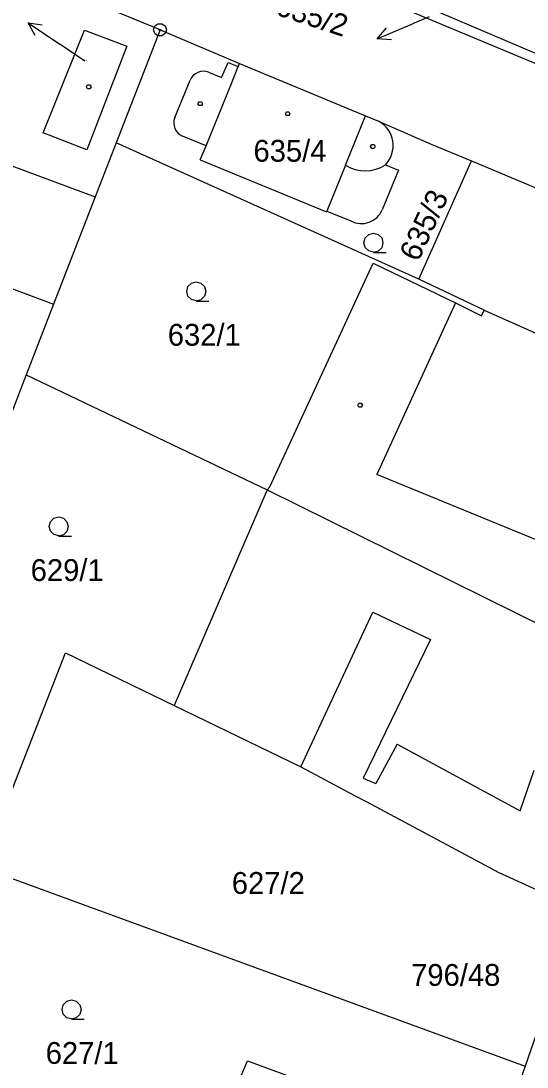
# Model space of a CAD drawing. Extents: x -759060 to -757386, y -1172273 to -1170948.
# Drawn here: x -758101.6 to -758062.1, y -1171430.9 to -1171349.3 of the extents above; entities that cross this region are included whole.
import ezdxf

# ---------------------------------------------------------------- set-up
doc = ezdxf.new("R2010")
doc.units = 0
for name, color, linetype in [('Vrstva 1', 7, 'Continuous'), ('Vrstva 12', 7, 'Continuous'), ('Vrstva 2', 7, 'Continuous'), ('Vrstva 3', 7, 'Continuous'), ('Vrstva 4', 7, 'Continuous'), ('Vrstva 5', 7, 'Continuous'), ('Vrstva 7', 7, 'Continuous'), ('Vrstva 8', 7, 'Continuous')]:
    doc.layers.add(name, color=color, linetype=linetype)

msp = doc.modelspace()

# ---------------------------------------------------------------- linework, layer by layer
at = {"layer": 'Vrstva 1'}
for p, q in [((-758090.74, -1171350.03), (-758125.45, -1171335.56)), ((-758062.42, -1171351.45), (-758087.08, -1171340.96)), ((-758087.4, -1171341.8), (-758056.26, -1171354.83)), ((-758090.74, -1171350.03), (-758094.16, -1171358.84)), ((-758090.74, -1171350.03), (-758084.54, -1171352.65)), ((-758099.84, -1171358.07), (-758096.62, -1171350.05)), ((-758096.62, -1171350.05), (-758093.33, -1171351.31)), ((-758093.33, -1171351.31), (-758096.44, -1171359.39)), ((-758060.58, -1171352.23), (-758062.42, -1171351.45)), ((-758085.96, -1171353.75), (-758085.43, -1171352.58)), ((-758085.43, -1171352.58), (-758084.64, -1171352.9)), ((-758084.64, -1171352.9), (-758084.54, -1171352.65)), ((-758084.54, -1171352.65), (-758074.71, -1171356.73)), ((-758120.75, -1171353.76), (-758095.79, -1171363.05)), ((-758089.59, -1171356.87), (-758088.39, -1171353.95)), ((-758086.95, -1171353.34), (-758085.96, -1171353.75)), ((-758074.71, -1171356.73), (-758073.7, -1171357.15)), ((-758073.7, -1171357.15), (-758069.6, -1171358.93)), ((-758096.44, -1171359.39), (-758099.84, -1171358.07)), ((-758094.16, -1171358.84), (-758095.79, -1171363.05)), ((-758070.57, -1171369.47), (-758094.16, -1171358.84)), ((-758087.15, -1171359.06), (-758088.98, -1171358.31)), ((-758069.6, -1171358.93), (-758066.46, -1171360.25)), ((-758087.61, -1171360.17), (-758087.15, -1171359.06)), ((-758087.61, -1171360.17), (-758077.76, -1171364.22)), ((-758073.17, -1171360.55), (-758072.14, -1171360.98)), ((-758070.57, -1171369.47), (-758066.46, -1171360.25)), ((-758066.46, -1171360.25), (-758041.29, -1171370.82)), ((-758072.14, -1171360.98), (-758073.41, -1171364.05)), ((-758124.01, -1171362.13), (-758099.04, -1171371.42)), ((-758095.79, -1171363.05), (-758099.04, -1171371.42)), ((-758077.76, -1171364.22), (-758077.73, -1171364.16)), ((-758077.73, -1171364.16), (-758075.86, -1171364.93)), ((-758082.19, -1171385.65), (-758074.13, -1171368.23)), ((-758074.13, -1171368.23), (-758067.71, -1171371.32)), ((-758065.47, -1171371.89), (-758070.57, -1171369.47)), ((-758099.04, -1171371.42), (-758101.17, -1171376.91)), ((-758067.71, -1171371.32), (-758065.69, -1171372.31)), ((-758065.69, -1171372.31), (-758065.47, -1171371.89)), ((-758065.47, -1171371.89), (-758058.25, -1171375.11)), ((-758101.17, -1171376.91), (-758102.3, -1171379.82)), ((-758101.17, -1171376.91), (-758082.38, -1171385.88)), ((-758082.38, -1171385.88), (-758089.63, -1171402.69)), ((-758082.38, -1171385.88), (-758082.19, -1171385.65)), ((-758082.38, -1171385.88), (-758060.53, -1171396.69)), ((-758103.6, -1171412.63), (-758098.12, -1171398.58)), ((-758098.12, -1171398.58), (-758089.63, -1171402.69)), ((-758089.63, -1171402.69), (-758079.76, -1171407.47)), ((-758079.76, -1171407.47), (-758075.57, -1171409.71)), ((-758075.57, -1171409.71), (-758074.67, -1171410.19)), ((-758074.67, -1171410.19), (-758064.32, -1171415.71)), ((-758104.44, -1171415.39), (-758062.28, -1171430.8)), ((-758064.32, -1171415.71), (-758058.05, -1171418.6)), ((-758058.05, -1171418.6), (-758062.28, -1171430.8)), ((-758087.25, -1171438.35), (-758083.93, -1171430.4)), ((-758083.93, -1171430.4), (-758079.26, -1171432.11)), ((-758062.28, -1171430.8), (-758064.57, -1171437.39))]:
    msp.add_line(p, q, dxfattribs=at)
for centre, radius, start, end in [((-758087.363, -1171354.37), 1.11, 68.15063, 157.76548), ((-758088.56, -1171357.283), 1.11, 158.15063, 247.76549), ((-758074.739, -1171359.053), 2.168, 316.33999, 61.3802), ((-758075.041, -1171363.361), 1.77, 242.424, 337.09092)]:
    msp.add_arc(centre, radius, start, end, dxfattribs=at)
at = {"layer": 'Vrstva 12'}
for p, q in [((-758099.84, -1171358.07), (-758096.62, -1171350.05)), ((-758096.62, -1171350.05), (-758093.33, -1171351.31)), ((-758093.33, -1171351.31), (-758096.44, -1171359.39)), ((-758085.12, -1171354.09), (-758084.64, -1171352.9)), ((-758084.64, -1171352.9), (-758084.54, -1171352.65)), ((-758084.54, -1171352.65), (-758074.71, -1171356.73)), ((-758087.15, -1171359.06), (-758085.12, -1171354.09)), ((-758076.27, -1171360.58), (-758074.71, -1171356.73)), ((-758096.44, -1171359.39), (-758099.84, -1171358.07)), ((-758087.61, -1171360.17), (-758087.15, -1171359.06)), ((-758087.61, -1171360.17), (-758077.76, -1171364.22)), ((-758076.27, -1171360.58), (-758077.73, -1171364.16)), ((-758077.76, -1171364.22), (-758077.73, -1171364.16)), ((-758079.76, -1171407.47), (-758074.14, -1171395.41)), ((-758074.14, -1171395.41), (-758069.66, -1171397.56)), ((-758069.66, -1171397.56), (-758074.91, -1171408.35)), ((-758072.25, -1171405.72), (-758073.91, -1171408.78)), ((-758072.25, -1171405.72), (-758062.67, -1171410.9)), ((-758079.76, -1171407.47), (-758075.57, -1171409.71)), ((-758062.67, -1171410.9), (-758061.56, -1171407.74)), ((-758074.91, -1171408.35), (-758073.91, -1171408.78)), ((-758075.57, -1171409.71), (-758074.67, -1171410.19)), ((-758074.67, -1171410.19), (-758064.32, -1171415.71)), ((-758064.32, -1171415.71), (-758058.05, -1171418.6))]:
    msp.add_line(p, q, dxfattribs=at)
at = {"layer": 'Vrstva 3'}
for points in [[(-758074.09, -1171367.36), (-758074.47, -1171367.26), (-758074.74, -1171366.99), (-758074.84, -1171366.62), (-758074.74, -1171366.25), (-758074.47, -1171365.98), (-758074.1, -1171365.88), (-758073.73, -1171365.98), (-758073.46, -1171366.25), (-758073.36, -1171366.63), (-758073.46, -1171367.01), (-758073.73, -1171367.28), (-758074.11, -1171367.38), (-758073.11, -1171367.38)], [(-758087.91, -1171371.15), (-758088.29, -1171371.05), (-758088.56, -1171370.78), (-758088.66, -1171370.41), (-758088.56, -1171370.04), (-758088.29, -1171369.77), (-758087.92, -1171369.67), (-758087.55, -1171369.77), (-758087.28, -1171370.04), (-758087.18, -1171370.42), (-758087.28, -1171370.8), (-758087.55, -1171371.07), (-758087.93, -1171371.17), (-758086.93, -1171371.17)], [(-758098.63, -1171389.48), (-758099.01, -1171389.38), (-758099.28, -1171389.11), (-758099.38, -1171388.74), (-758099.28, -1171388.37), (-758099.01, -1171388.1), (-758098.64, -1171388), (-758098.27, -1171388.1), (-758098, -1171388.37), (-758097.9, -1171388.75), (-758098, -1171389.13), (-758098.27, -1171389.4), (-758098.65, -1171389.5), (-758097.65, -1171389.5)], [(-758097.63, -1171427.13), (-758098.01, -1171427.03), (-758098.28, -1171426.76), (-758098.38, -1171426.39), (-758098.28, -1171426.02), (-758098.01, -1171425.75), (-758097.64, -1171425.65), (-758097.27, -1171425.75), (-758097, -1171426.02), (-758096.9, -1171426.4), (-758097, -1171426.78), (-758097.27, -1171427.05), (-758097.65, -1171427.15), (-758096.65, -1171427.15)]]:
    msp.add_lwpolyline(points, dxfattribs=at)
at = {"layer": 'Vrstva 4'}
for p, q in [((-758085.12, -1171354.09), (-758084.64, -1171352.9)), ((-758087.15, -1171359.06), (-758085.12, -1171354.09)), ((-758076.27, -1171360.58), (-758074.71, -1171356.73)), ((-758076.27, -1171360.58), (-758077.73, -1171364.16)), ((-758067.71, -1171371.32), (-758073.83, -1171384.7)), ((-758058.43, -1171391), (-758073.83, -1171384.7)), ((-758079.76, -1171407.47), (-758074.14, -1171395.41)), ((-758074.14, -1171395.41), (-758069.66, -1171397.56)), ((-758069.66, -1171397.56), (-758074.91, -1171408.35)), ((-758072.25, -1171405.72), (-758073.91, -1171408.78)), ((-758072.25, -1171405.72), (-758062.67, -1171410.9)), ((-758062.67, -1171410.9), (-758061.56, -1171407.74)), ((-758074.91, -1171408.35), (-758073.91, -1171408.78))]:
    msp.add_line(p, q, dxfattribs=at)
msp.add_arc((-758074.744, -1171358.123), 2.893, 238.15501, 302.95391, dxfattribs=at)
at = {"layer": 'Vrstva 5'}
for points in [[(-758096.21, -1171354.32), (-758096.12, -1171354.47), (-758096.21, -1171354.62), (-758096.39, -1171354.62), (-758096.48, -1171354.47), (-758096.39, -1171354.32)], [(-758087.51, -1171355.64), (-758087.42, -1171355.79), (-758087.51, -1171355.94), (-758087.69, -1171355.94), (-758087.78, -1171355.79), (-758087.69, -1171355.64)], [(-758080.7, -1171356.42), (-758080.61, -1171356.57), (-758080.7, -1171356.72), (-758080.88, -1171356.72), (-758080.97, -1171356.57), (-758080.88, -1171356.42)], [(-758074.05, -1171358.98), (-758073.96, -1171359.13), (-758074.05, -1171359.28), (-758074.23, -1171359.28), (-758074.32, -1171359.13), (-758074.23, -1171358.98)], [(-758075.05, -1171379.14), (-758074.96, -1171379.29), (-758075.05, -1171379.44), (-758075.23, -1171379.44), (-758075.32, -1171379.29), (-758075.23, -1171379.14)]]:
    msp.add_lwpolyline(points, close=True, dxfattribs=at)
at = {"layer": 'Vrstva 7'}
for p, q in [((-758069.76, -1171349.01), (-758071.06, -1171349.56)), ((-758101.033, -1171349.491), (-758098.54, -1171351.16)), ((-758073.822, -1171350.732), (-758071.06, -1171349.56)), ((-758096.59, -1171352.46), (-758098.54, -1171351.16))]:
    msp.add_line(p, q, dxfattribs=at)
for points in [[(-758100.48, -1171350.463), (-758101.033, -1171349.491), (-758099.924, -1171349.632)], [(-758072.706, -1171350.801), (-758073.822, -1171350.732), (-758073.096, -1171349.881)]]:
    msp.add_lwpolyline(points, dxfattribs=at)
at = {"layer": 'Vrstva 8'}
msp.add_line((-758090.86, -1171350.03), (-758090.62, -1171350.03), dxfattribs=at)
msp.add_lwpolyline([(-758090.59, -1171349.55), (-758090.34, -1171349.73), (-758090.24, -1171350.02), (-758090.34, -1171350.31), (-758090.59, -1171350.49), (-758090.9, -1171350.49), (-758091.15, -1171350.31), (-758091.25, -1171350.02), (-758091.15, -1171349.73), (-758090.9, -1171349.55)], close=True, dxfattribs=at)

# ---------------------------------------------------------------- texts
at = {"layer": 'Vrstva 2'}
for s, height, p in [('636/4', 0.1, (-758096.797, -1171352.46)), ('635/4', 1.7, (-758083.453, -1171360.31)), ('632/1', 1.7, (-758090.133, -1171374.65)), ('629/1', 1.7, (-758100.823, -1171392.99)), ('627/2', 1.7, (-758085.143, -1171417.38)), ('627/1', 1.7, (-758099.653, -1171430.63))]:
    msp.add_text(s, height=height, dxfattribs=at).set_placement(p)
msp.add_text('635/3', height=1.7, rotation=65.08801, dxfattribs=at).set_placement((-758070.609, -1171368.184))
at = {"layer": 'Vrstva 7'}
msp.add_text('635/2', height=1.7, rotation=341.76933, dxfattribs=at).set_placement((-758081.844, -1171348.812))
msp.add_text('796/48', height=1.7, dxfattribs=at).set_placement((-758071.163, -1171424.55))

doc.saveas('drawing.dxf')
